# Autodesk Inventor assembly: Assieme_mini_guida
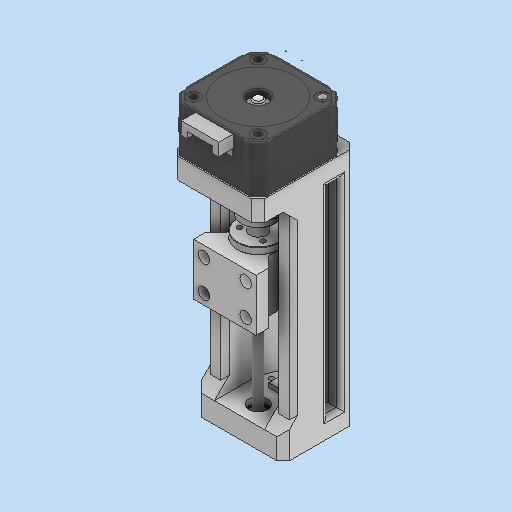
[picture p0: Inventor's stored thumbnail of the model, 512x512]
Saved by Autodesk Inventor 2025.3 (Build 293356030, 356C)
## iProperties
Created: 2025-12
Part Number: Assieme_mini_guida
Document SubType Name: Assembly
Designer: Ryzen5700u
Author: Ryzen5700u
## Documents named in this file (9)
- C:\Users\R5800u\Desktop\guida small\Assieme_mini_guida.iam
- C:\Users\R5800u\Desktop\guida small\t4 nut dado.ipt
- C:\Users\R5800u\Desktop\guida small\barra T4.ipt
- C:\Users\R5800u\Desktop\guida small\nema17_23mm.ipt
- C:\Users\R5800u\Desktop\guida small\blocco_barre.ipt
- C:\Users\R5800u\Desktop\guida small\frame.ipt
- C:\Users\R5800u\Desktop\guida small\barra_6mm.ipt
- C:\Users\R5800u\Desktop\guida small\dado_barra.ipt
- C:\Users\R5800u\Documents\Inventor\Content Center Files\R2025\it-IT\BS 290 SKF(30)\BS 290 SKF - SKF 604.ipt
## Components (8 placed, 8 different names)
1. t4 nut dado:1 — Coincidente:1, Angolo:3, Coincidente:9, Allineato:2
2. barra T4:1 — Coincidente:1, Coincidente:2, Coincidente:3, Coincidente:4
3. nema17_23mm:1 — Coincidente:2, Coincidente:3, Angolo:1, Coincidente:5, Coincidente:6, Angolo:2, Coincidente:7, Coincidente:8, Allineato:1, Angolo:3
4. blocco_barre:1 — Coincidente:4, Coincidente:5, Coincidente:9
5. barra_6mm:1 — Rotazionale:1
6. frame:1 — Coincidente:6, Angolo:2, Coincidente:7, Coincidente:8, Rotazionale:1, Rotazionale:2
7. dado_barra:1 — Allineato:2
8. BS 290 SKF 604:1 — Rotazionale:2
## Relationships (16: Mate 9, Angle 3, RevoluteJoint 2, Flush 2)
- Coincidente:1 [Mate]: t4 nut dado:1 ↔ barra T4:1
- Coincidente:2 [Mate]: barra T4:1 ↔ nema17_23mm:1
- Coincidente:3 [Mate]: barra T4:1 ↔ nema17_23mm:1
- Angolo:1 [Angle]: nema17_23mm:1
- Coincidente:4 [Mate]: barra T4:1 ↔ blocco_barre:1
- Coincidente:5 [Mate]: nema17_23mm:1 ↔ blocco_barre:1
- Coincidente:6 [Mate]: nema17_23mm:1 ↔ frame:1
- Angolo:2 [Angle]: nema17_23mm:1 ↔ frame:1
- Coincidente:7 [Mate]: nema17_23mm:1 ↔ frame:1
- Coincidente:8 [Mate]: nema17_23mm:1 ↔ frame:1
- Rotazionale:1 [RevoluteJoint]: barra_6mm:1 ↔ frame:1
- Allineato:1 [Flush]: nema17_23mm:1
- Angolo:3 [Angle]: t4 nut dado:1 ↔ nema17_23mm:1
- Coincidente:9 [Mate]: t4 nut dado:1 ↔ blocco_barre:1
- Allineato:2 [Flush]: t4 nut dado:1 ↔ dado_barra:1
- Rotazionale:2 [RevoluteJoint]: frame:1 ↔ BS 290 SKF 604:1
